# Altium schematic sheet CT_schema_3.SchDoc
size 257 x 245 mm
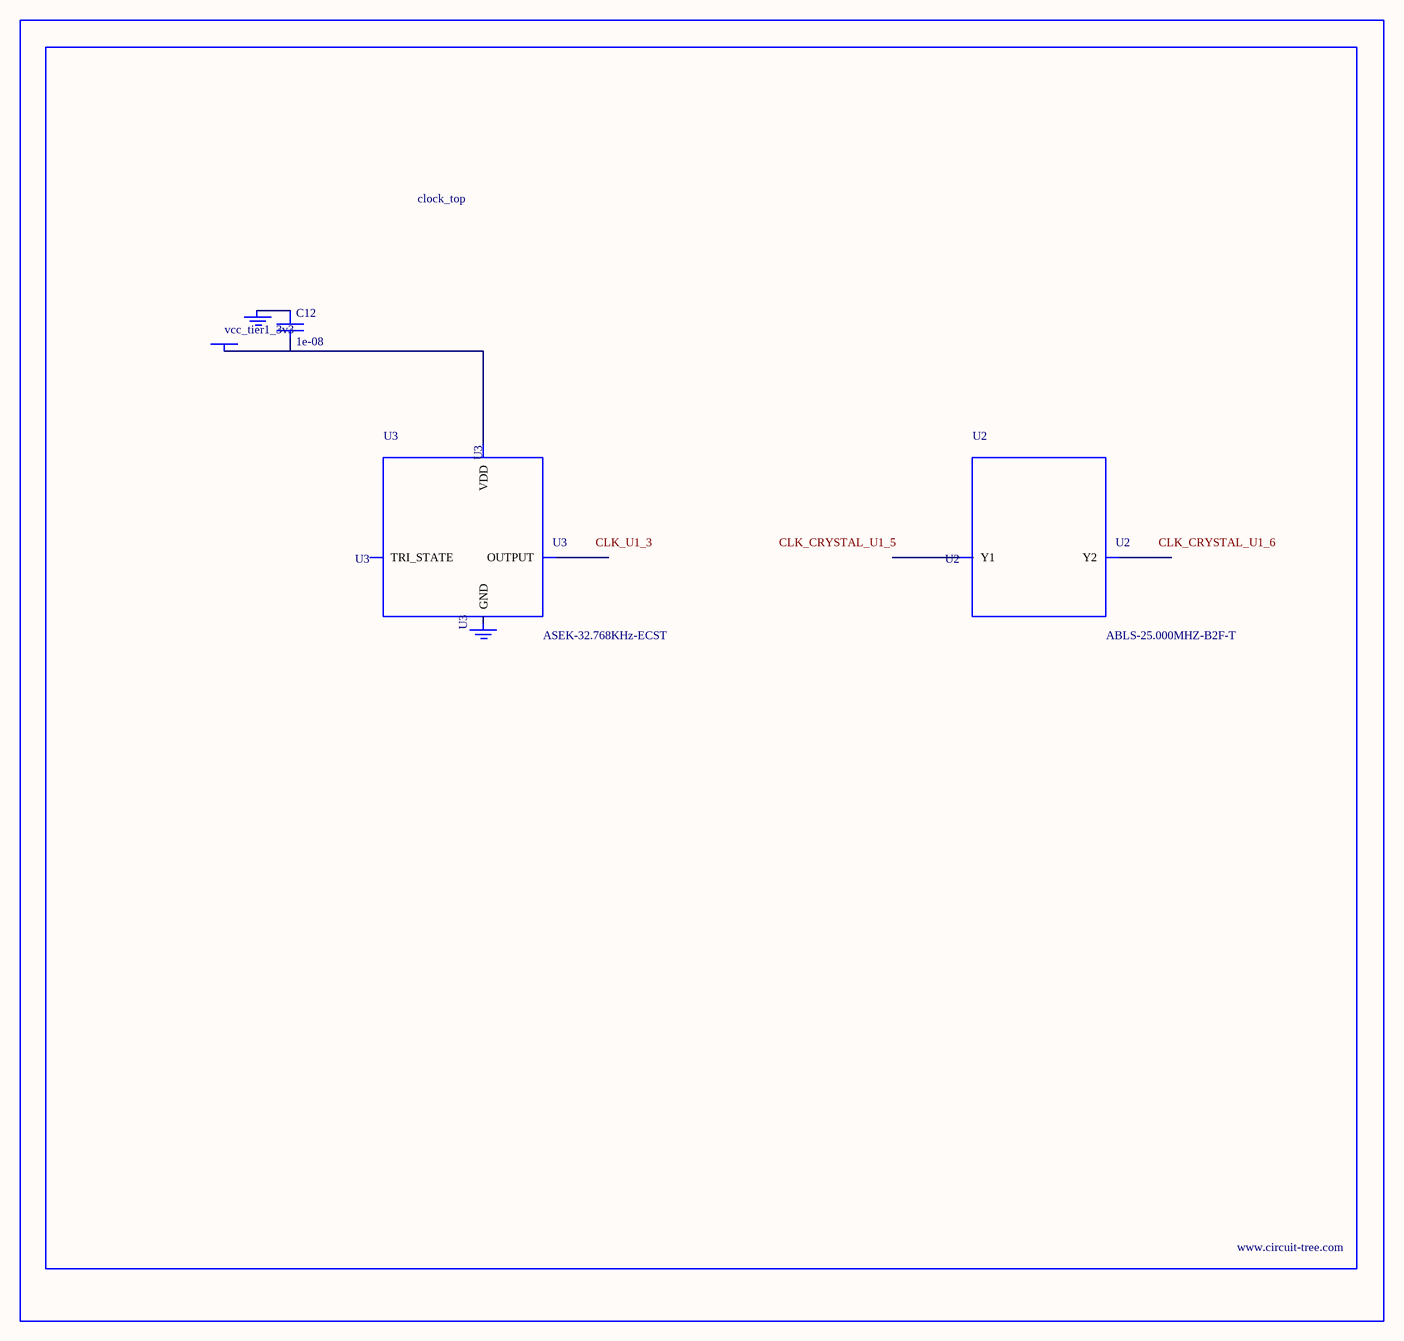
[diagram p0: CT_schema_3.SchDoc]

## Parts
BORDER2  (no value)
C12  1e-08  [C0402]
GND_INSTANCE_2_0  (no value)
GND_INSTANCE_2_1  (no value)
POWER_INSTANCE_2_0  vcc_tier1_3v3
U2  ABLS-25.000MHZ-B2F-T  [ABLS-25.000MHZ-B2F-T]
U3  ASEK-32.768KHz-ECST  [ASEK]

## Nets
NetC12_1: C12.1 GND_INSTANCE_2_0.0(GND)
NetC12_2: C12.2 POWER_INSTANCE_2_0.0(PWR) U3.4(VDD)

Not connected (* = marked no-connect by the designer): GND_INSTANCE_2_1 0(GND); U2 1(Y1) 2(Y2); U3 1(TRI_STATE) 2(GND) 3(OUTPUT)

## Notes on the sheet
- Labels drawn without touching a wire or pin: CLK_CRYSTAL_U1_5, CLK_CRYSTAL_U1_6, CLK_U1_3

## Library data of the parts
BORDER2 = BORDER_PAGE2
C12 = C0402C103K3RAC
GND_INSTANCE_2_0 GND_INSTANCE_2_1 = GND
POWER_INSTANCE_2_0 = PWR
